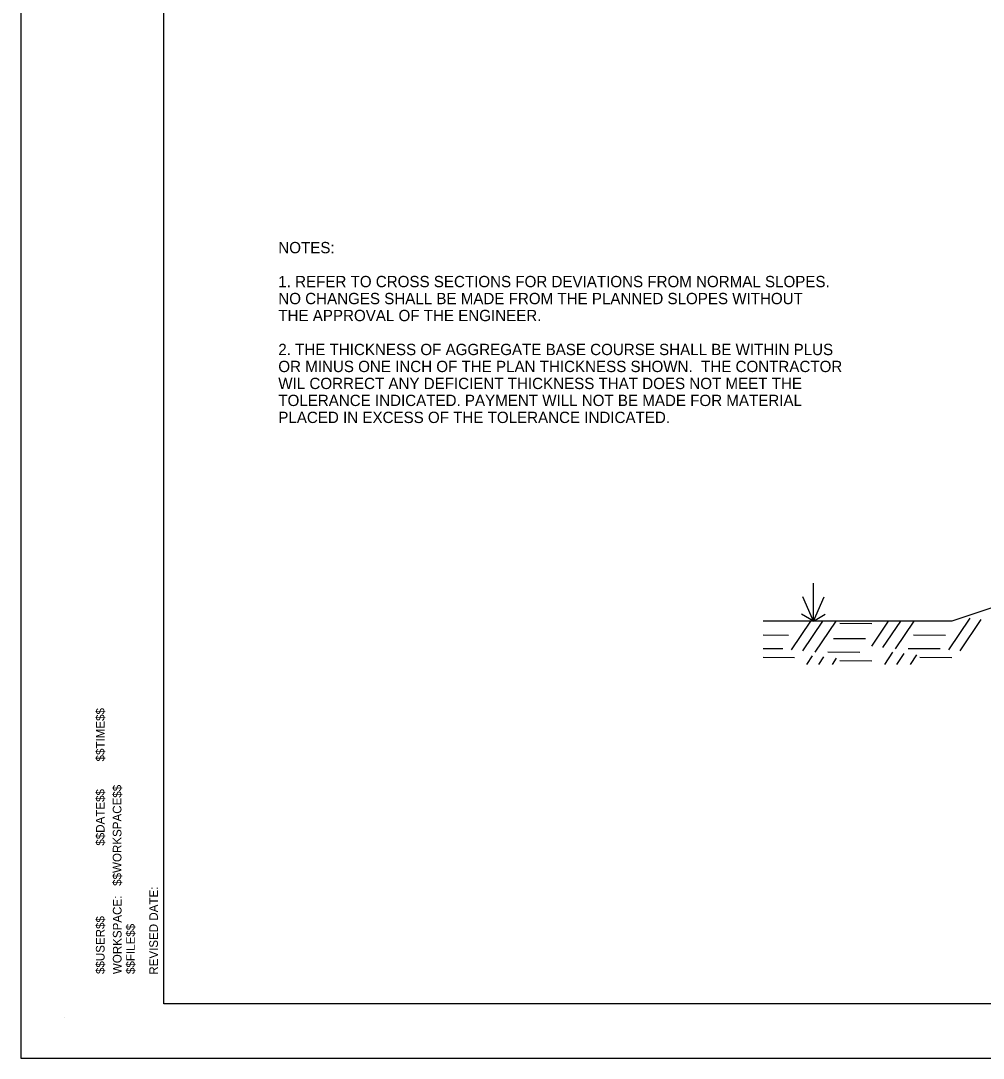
# Model space of a CAD drawing. Extents: x 2478 to 3210, y 439 to 841.
# Drawn here: x 2870.4 to 2972.5, y 438.6 to 548.6 of the extents above; entities that cross this region are included whole.
import ezdxf

# ---------------------------------------------------------------- set-up
doc = ezdxf.new("R2010")
doc.units = 0
for name, color, linetype in [('1', 7, 'Continuous'), ('R_Annotation', 7, 'Continuous'), ('R_Dimension', 7, 'Continuous'), ('R_Draft', 7, 'Continuous')]:
    doc.layers.add(name, color=color, linetype=linetype)

msp = doc.modelspace()

# ---------------------------------------------------------------- linework, layer by layer
at = {"layer": '1'}
for p, q in [((2885.53, 444.35), (2885.53, 652.81)), ((3204.6, 444.35), (2885.53, 444.35)), ((2875.05, 442.86), (2875.05, 442.86))]:
    msp.add_line(p, q, dxfattribs=at)
for points in [[(3210.37, 658.58), (2870.37, 658.58), (2870.37, 438.58), (3210.37, 438.58)], [(2885.53, 444.35), (2885.53, 652.81), (3122.34, 652.81), (3122.34, 642.93), (3161.5, 642.93), (3161.5, 640.01), (3204.6, 640.01), (3204.6, 444.35)]]:
    msp.add_lwpolyline(points, close=True, dxfattribs=at)
at = {"layer": 'R_Annotation'}
for p, q in [((3008.39, 498.01), (2969.13, 484.93)), ((2969.13, 484.93), (2949.13, 484.93))]:
    msp.add_line(p, q, dxfattribs=at)
at = {"layer": 'R_Dimension'}
for p, q in [((2968.81, 481.9), (2971.06, 485.24)), ((2970, 481.77), (2972.26, 485.1)), ((2952.12, 481.9), (2954.16, 484.93)), ((2953.32, 481.77), (2955.45, 484.93)), ((2954.65, 481.63), (2956.88, 484.93)), ((2957.24, 484.71), (2960.63, 484.69)), ((2960.63, 482.27), (2962.43, 484.93)), ((2961.83, 482.13), (2963.72, 484.93)), ((2963.16, 481.99), (2965.14, 484.93)), ((2949.13, 483.46), (2951.79, 483.43)), ((2956.57, 483.1), (2959.96, 483.07)), ((2965.08, 483.46), (2968.47, 483.43)), ((2949.13, 482.03), (2951.2, 482.02)), ((2964.5, 482.04), (2967.89, 482.02)), ((2949.13, 481.1), (2952.46, 481.07)), ((2953.74, 480.33), (2954.37, 481.26)), ((2955.03, 480.33), (2955.57, 481.13)), ((2955.99, 481.68), (2959.38, 481.65)), ((2956.46, 480.33), (2956.91, 480.99)), ((2957.24, 480.74), (2960.63, 480.71)), ((2962.01, 480.33), (2962.88, 481.63)), ((2963.3, 480.33), (2964.08, 481.49)), ((2964.73, 480.33), (2965.42, 481.35)), ((2965.75, 481.1), (2969.14, 481.07))]:
    msp.add_line(p, q, dxfattribs=at)
at = {"layer": 'R_Draft'}
for q in [(2954.46, 488.94), (2953.32, 487.51), (2955.59, 487.51), (2953.2, 485.68), (2955.71, 485.68)]:
    msp.add_line((2954.46, 484.93), q, dxfattribs=at)

# ---------------------------------------------------------------- texts
at = {"layer": '1'}
for s, p in [('$$TIME$$', (2879.26, 470.05)), ('$$WORKSPACE$$', (2881.05, 456.86)), ('$$DATE$$', (2879.26, 461.12)), ('REVISED DATE:', (2884.92, 447.44)), ('WORKSPACE:', (2881.06, 447.5)), ('$$USER$$', (2879.26, 447.51)), ('$$FILE$$', (2882.47, 447.51))]:
    msp.add_text(s, height=0.918, rotation=90, dxfattribs=at).set_placement(p)
at = {"layer": 'R_Annotation'}
for s, p in [('NOTES:', (2897.69, 523.93)), ('1. REFER TO CROSS SECTIONS FOR DEVIATIONS FROM NORMAL SLOPES. ', (2897.69, 520.33)), ('NO CHANGES SHALL BE MADE FROM THE PLANNED SLOPES WITHOUT', (2897.69, 518.53)), ('THE APPROVAL OF THE ENGINEER.', (2897.69, 516.73)), ('2. THE THICKNESS OF AGGREGATE BASE COURSE SHALL BE WITHIN PLUS ', (2897.69, 513.13)), ('OR MINUS ONE INCH OF THE PLAN THICKNESS SHOWN.  THE CONTRACTOR', (2897.69, 511.33)), ('WIL CORRECT ANY DEFICIENT THICKNESS THAT DOES NOT MEET THE ', (2897.69, 509.53)), ('TOLERANCE INDICATED. PAYMENT WILL NOT BE MADE FOR MATERIAL ', (2897.69, 507.73)), ('PLACED IN EXCESS OF THE TOLERANCE INDICATED.', (2897.69, 505.93))]:
    msp.add_text(s, height=1.2, dxfattribs=at).set_placement(p)

doc.saveas('drawing.dxf')
